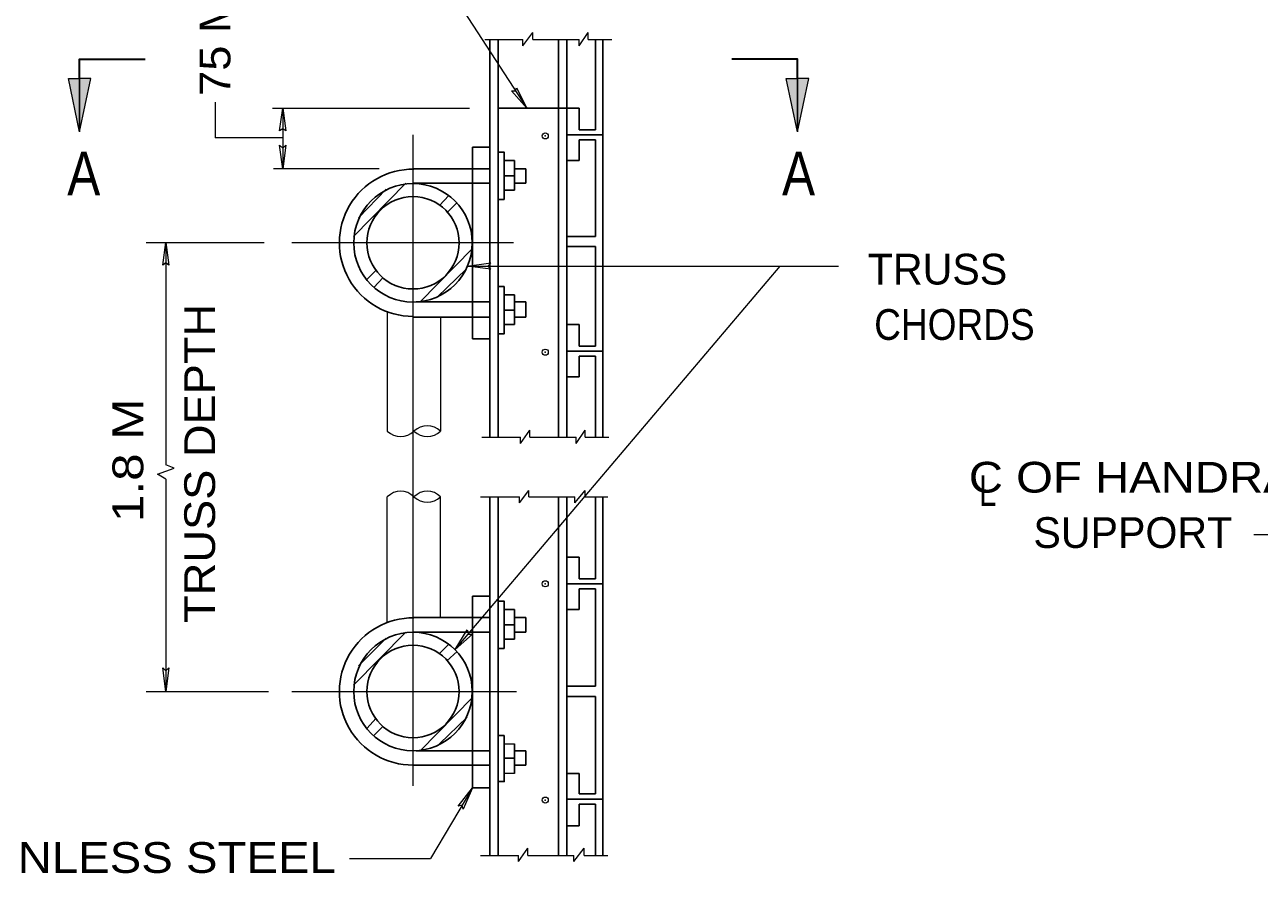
# Model space of a CAD drawing. Extents: x 312601.858 to 312602.699, y 144420.109 to 144420.704.
# Drawn here: x 312601.9234 to 312602.0438, y 144420.5352 to 144420.6179 of the extents above; entities that cross this region are included whole.
import ezdxf
from ezdxf.enums import TextEntityAlignment as Align

# ---------------------------------------------------------------- set-up
doc = ezdxf.new("R2010")
doc.units = 0
doc.header["$LTSCALE"] = 0.0012
doc.header["$PDMODE"] = 32
doc.header["$PDSIZE"] = 0.0006
doc.linetypes.add('DOT_DASHED', pattern=[7.7, 5, -1.2, 0.3, -1.2])
doc.linetypes.add('MEDIUM_DASHED', pattern=[4.5, 3, -1.5])
for name, color, linetype, lineweight in [('1', 7, 'Continuous', 13), ('2', 7, 'Continuous', 13), ('5', 7, 'Continuous', 25)]:
    doc.layers.add(name, color=color, linetype=linetype, lineweight=lineweight)

msp = doc.modelspace()

# ---------------------------------------------------------------- hatches: boundary and pattern name
at = {"layer": '1'}
for points in [[(312601.9277, 144420.6127), (312601.9288, 144420.6127), (312601.9288, 144420.6075)], [(312601.9299, 144420.6127), (312601.9288, 144420.6127), (312601.9288, 144420.6075)], [(312601.9977, 144420.6127), (312601.9988, 144420.6127), (312601.9988, 144420.6075)], [(312601.9999, 144420.6127), (312601.9988, 144420.6127), (312601.9988, 144420.6075)]]:
    msp.add_hatch(color=256, dxfattribs=at).paths.add_polyline_path(points)

# ---------------------------------------------------------------- linework, layer by layer
for p, q in [((312601.9586, 144420.6311), (312601.9724, 144420.6098)), ((312601.9683, 144420.6165), (312601.972, 144420.6165)), ((312601.972, 144420.6159), (312601.973, 144420.6172)), ((312601.972, 144420.6159), (312601.972, 144420.6165)), ((312601.973, 144420.6165), (312601.973, 144420.6172)), ((312601.973, 144420.6165), (312601.9775, 144420.6165)), ((312601.9775, 144420.6159), (312601.9784, 144420.6172)), ((312601.9775, 144420.6159), (312601.9775, 144420.6165)), ((312601.9784, 144420.6165), (312601.9784, 144420.6172)), ((312601.9784, 144420.6165), (312601.9807, 144420.6165)), ((312601.9288, 144420.6077), (312601.9288, 144420.6145)), ((312601.9988, 144420.6077), (312601.9988, 144420.6145)), ((312601.942, 144420.6104), (312601.942, 144420.6069)), ((312601.9476, 144420.6098), (312601.9668, 144420.6098)), ((312601.9486, 144420.6098), (312601.9486, 144420.6039)), ((312601.958, 144420.6039), (312601.9477, 144420.6039)), ((312601.9555, 144420.5973), (312601.9606, 144420.6025)), ((312601.956, 144420.5991), (312601.9587, 144420.6019)), ((312601.9639, 144420.6003), (312601.9648, 144420.6013)), ((312601.9646, 144420.5996), (312601.9656, 144420.6006)), ((312601.9353, 144420.5967), (312601.9468, 144420.5967)), ((312601.9372, 144420.5967), (312601.9372, 144420.575)), ((312601.962, 144420.5909), (312601.9671, 144420.5961)), ((312601.9568, 144420.5931), (312601.9577, 144420.594)), ((312601.9637, 144420.5914), (312601.9665, 144420.5941)), ((312601.9654, 144420.557), (312601.9971, 144420.5944)), ((312601.9666, 144420.5944), (312602.0028, 144420.5944)), ((312601.9575, 144420.5923), (312601.9584, 144420.5933)), ((312601.9588, 144420.59), (312601.9588, 144420.5783)), ((312601.964, 144420.5894), (312601.964, 144420.5783)), ((312601.9718, 144420.5771), (312601.9727, 144420.5784)), ((312601.9727, 144420.5777), (312601.9727, 144420.5784)), ((312601.9772, 144420.5771), (312601.9781, 144420.5784)), ((312601.9781, 144420.5777), (312601.9781, 144420.5784)), ((312601.968, 144420.5777), (312601.9718, 144420.5777)), ((312601.9718, 144420.5771), (312601.9718, 144420.5777)), ((312601.9727, 144420.5777), (312601.9772, 144420.5777)), ((312601.9772, 144420.5771), (312601.9772, 144420.5777)), ((312601.9781, 144420.5777), (312601.9804, 144420.5777)), ((312601.9372, 144420.5736), (312601.9372, 144420.5529)), ((312601.9588, 144420.5596), (312601.9588, 144420.5719)), ((312601.964, 144420.5601), (312601.964, 144420.5719)), ((312601.9679, 144420.5719), (312601.9717, 144420.5719)), ((312601.9717, 144420.5713), (312601.9726, 144420.5725)), ((312601.9717, 144420.5713), (312601.9717, 144420.5719)), ((312601.9726, 144420.5719), (312601.9726, 144420.5725)), ((312601.9726, 144420.5719), (312601.9771, 144420.5719)), ((312601.9771, 144420.5713), (312601.9781, 144420.5725)), ((312601.9771, 144420.5713), (312601.9771, 144420.5719)), ((312601.9781, 144420.5719), (312601.9781, 144420.5725)), ((312601.9781, 144420.5719), (312601.9803, 144420.5719)), ((312602.0433, 144420.5682), (312602.0595, 144420.5682)), ((312601.9555, 144420.5535), (312601.9606, 144420.5587)), ((312601.956, 144420.5554), (312601.9587, 144420.5581)), ((312601.9639, 144420.5566), (312601.9648, 144420.5575)), ((312601.9646, 144420.5559), (312601.9656, 144420.5568)), ((312601.9353, 144420.5529), (312601.9472, 144420.5529)), ((312601.962, 144420.5471), (312601.9671, 144420.5523)), ((312601.9568, 144420.5493), (312601.9577, 144420.5503)), ((312601.9639, 144420.5478), (312601.9666, 144420.5504)), ((312601.9575, 144420.5486), (312601.9584, 144420.5495)), ((312601.9702, 144420.5478), (312601.9712, 144420.5478)), ((312601.9712, 144420.5449), (312601.9702, 144420.5449)), ((312601.9671, 144420.5435), (312601.963, 144420.5366)), ((312601.9716, 144420.5363), (312601.9725, 144420.5376)), ((312601.9725, 144420.5369), (312601.9725, 144420.5376)), ((312601.977, 144420.5363), (312601.978, 144420.5376)), ((312601.978, 144420.5369), (312601.978, 144420.5376)), ((312601.9551, 144420.5366), (312601.963, 144420.5366)), ((312601.9679, 144420.5369), (312601.9716, 144420.5369)), ((312601.9716, 144420.5363), (312601.9716, 144420.5369)), ((312601.9725, 144420.5369), (312601.977, 144420.5369)), ((312601.977, 144420.5363), (312601.977, 144420.5369)), ((312601.978, 144420.5369), (312601.9803, 144420.5369))]:
    msp.add_line(p, q, dxfattribs=at)
at = {"layer": '1', "lineweight": 25}
for p, q in [((312601.9688, 144420.6165), (312601.9688, 144420.5777)), ((312601.9696, 144420.6165), (312601.9696, 144420.5777)), ((312601.9755, 144420.6165), (312601.9755, 144420.5777)), ((312601.9763, 144420.6165), (312601.9763, 144420.5777)), ((312601.9791, 144420.6165), (312601.9791, 144420.6077)), ((312601.9798, 144420.6165), (312601.9798, 144420.5777)), ((312601.9696, 144420.6098), (312601.9775, 144420.6098)), ((312601.9775, 144420.6098), (312601.9775, 144420.6077)), ((312601.9775, 144420.6077), (312601.9791, 144420.6077)), ((312601.9671, 144420.606), (312601.9688, 144420.606)), ((312601.9671, 144420.606), (312601.9671, 144420.5873)), ((312601.9775, 144420.6067), (312601.9791, 144420.6067)), ((312601.9775, 144420.6067), (312601.9775, 144420.6047)), ((312601.9791, 144420.6067), (312601.9791, 144420.5973)), ((312601.9702, 144420.6047), (312601.9712, 144420.6047)), ((312601.9712, 144420.6047), (312601.9712, 144420.6018)), ((312601.9775, 144420.6047), (312601.9763, 144420.6047)), ((312601.967, 144420.6039), (312601.9613, 144420.6039)), ((312601.9712, 144420.6032), (312601.9702, 144420.6032)), ((312601.9712, 144420.6039), (312601.9723, 144420.6039)), ((312601.9723, 144420.6039), (312601.9723, 144420.6025)), ((312601.9613, 144420.6025), (312601.9671, 144420.6025)), ((312601.9712, 144420.6025), (312601.9723, 144420.6025)), ((312601.9696, 144420.6009), (312601.9702, 144420.6009)), ((312601.9702, 144420.6018), (312601.9712, 144420.6018)), ((312601.9763, 144420.5973), (312601.9791, 144420.5973)), ((312601.9763, 144420.5963), (312601.9791, 144420.5963)), ((312601.9791, 144420.5963), (312601.9791, 144420.5866)), ((312601.9696, 144420.5924), (312601.9702, 144420.5924)), ((312601.9702, 144420.5916), (312601.9712, 144420.5916)), ((312601.9712, 144420.5887), (312601.9712, 144420.5916)), ((312601.9616, 144420.5909), (312601.9671, 144420.5909)), ((312601.9712, 144420.5901), (312601.9702, 144420.5901)), ((312601.9712, 144420.5909), (312601.9723, 144420.5909)), ((312601.9723, 144420.5894), (312601.9723, 144420.5909)), ((312601.9613, 144420.5894), (312601.9671, 144420.5894)), ((312601.9712, 144420.5887), (312601.9702, 144420.5887)), ((312601.9712, 144420.5894), (312601.9723, 144420.5894)), ((312601.9763, 144420.5887), (312601.9775, 144420.5887)), ((312601.9775, 144420.5887), (312601.9775, 144420.5866)), ((312601.9671, 144420.5873), (312601.9688, 144420.5873)), ((312601.9775, 144420.5866), (312601.9791, 144420.5866)), ((312601.9763, 144420.5861), (312601.9798, 144420.5861)), ((312601.9775, 144420.5856), (312601.9791, 144420.5856)), ((312601.9775, 144420.5856), (312601.9775, 144420.5836)), ((312601.9791, 144420.5856), (312601.9791, 144420.5777)), ((312601.9775, 144420.5836), (312601.9763, 144420.5836)), ((312601.9688, 144420.5719), (312601.9688, 144420.5369)), ((312601.9696, 144420.5719), (312601.9696, 144420.5369)), ((312601.9755, 144420.5719), (312601.9755, 144420.5369)), ((312601.9763, 144420.5719), (312601.9763, 144420.5369)), ((312601.9791, 144420.5719), (312601.9791, 144420.5639)), ((312601.9798, 144420.5719), (312601.9798, 144420.5369)), ((312601.9763, 144420.566), (312601.9775, 144420.566)), ((312601.9775, 144420.566), (312601.9775, 144420.5639)), ((312601.9775, 144420.5639), (312601.9791, 144420.5639)), ((312601.9671, 144420.5622), (312601.9688, 144420.5622)), ((312601.9671, 144420.5622), (312601.9671, 144420.5435)), ((312601.9763, 144420.5634), (312601.9798, 144420.5634)), ((312601.9775, 144420.5629), (312601.9791, 144420.5629)), ((312601.9775, 144420.5629), (312601.9775, 144420.5609)), ((312601.9791, 144420.5629), (312601.9791, 144420.5534)), ((312601.9613, 144420.5601), (312601.9671, 144420.5601)), ((312601.9702, 144420.5609), (312601.9712, 144420.5609)), ((312601.9712, 144420.5609), (312601.9712, 144420.558)), ((312601.9712, 144420.5601), (312601.9723, 144420.5601)), ((312601.9723, 144420.5601), (312601.9723, 144420.5587)), ((312601.9775, 144420.5609), (312601.9763, 144420.5609)), ((312601.9613, 144420.5587), (312601.9671, 144420.5587)), ((312601.9712, 144420.5594), (312601.9702, 144420.5594)), ((312601.9712, 144420.5587), (312601.9723, 144420.5587)), ((312601.9702, 144420.558), (312601.9712, 144420.558)), ((312601.9696, 144420.5571), (312601.9702, 144420.5571)), ((312601.9763, 144420.5534), (312601.9791, 144420.5534)), ((312601.9763, 144420.5524), (312601.9791, 144420.5524)), ((312601.9791, 144420.5524), (312601.9791, 144420.5429)), ((312601.9696, 144420.5486), (312601.9702, 144420.5486)), ((312601.9712, 144420.5449), (312601.9712, 144420.5478)), ((312601.9616, 144420.5471), (312601.9671, 144420.5471)), ((312601.9712, 144420.5471), (312601.9723, 144420.5471)), ((312601.9723, 144420.5457), (312601.9723, 144420.5471)), ((312601.9613, 144420.5457), (312601.9671, 144420.5457)), ((312601.9712, 144420.5464), (312601.9702, 144420.5464)), ((312601.9712, 144420.5457), (312601.9723, 144420.5457)), ((312601.9763, 144420.5449), (312601.9775, 144420.5449)), ((312601.9775, 144420.5449), (312601.9775, 144420.5429)), ((312601.9671, 144420.5435), (312601.9688, 144420.5435)), ((312601.9763, 144420.5424), (312601.9798, 144420.5424)), ((312601.9775, 144420.5429), (312601.9791, 144420.5429)), ((312601.9775, 144420.5419), (312601.9791, 144420.5419)), ((312601.9775, 144420.5419), (312601.9775, 144420.5398)), ((312601.9791, 144420.5419), (312601.9791, 144420.5369)), ((312601.9775, 144420.5398), (312601.9763, 144420.5398))]:
    msp.add_line(p, q, dxfattribs=at)
at = {"layer": '1', "linetype": 'DOT_DASHED'}
for p, q in [((312601.9613, 144420.6072), (312601.9613, 144420.5437)), ((312601.9495, 144420.5967), (312601.9711, 144420.5967)), ((312601.9495, 144420.5529), (312601.9714, 144420.5529))]:
    msp.add_line(p, q, dxfattribs=at)
at = {"layer": '1', "linetype": 'MEDIUM_DASHED', "lineweight": 25}
for p, q in [((312601.9671, 144420.6039), (312601.9688, 144420.6039)), ((312601.9671, 144420.6025), (312601.9688, 144420.6025)), ((312601.9671, 144420.5909), (312601.9688, 144420.5909)), ((312601.9671, 144420.5894), (312601.9688, 144420.5894)), ((312601.9671, 144420.5601), (312601.9688, 144420.5601)), ((312601.9671, 144420.5587), (312601.9688, 144420.5587)), ((312601.9671, 144420.5471), (312601.9688, 144420.5471)), ((312601.9671, 144420.5457), (312601.9688, 144420.5457))]:
    msp.add_line(p, q, dxfattribs=at)
at = {"layer": '1', "lineweight": 35}
for points in [[(312601.9288, 144420.6127), (312601.9288, 144420.6146), (312601.9352, 144420.6146)], [(312601.9988, 144420.6127), (312601.9988, 144420.6146), (312601.9924, 144420.6146)]]:
    msp.add_lwpolyline(points, dxfattribs=at)
at = {"layer": '1'}
for points in [[(312601.9277, 144420.6127), (312601.9288, 144420.6127), (312601.9288, 144420.6075)], [(312601.9299, 144420.6127), (312601.9288, 144420.6127), (312601.9288, 144420.6075)], [(312601.9714, 144420.6118), (312601.9724, 144420.6098), (312601.9709, 144420.6115), (312601.9713, 144420.6115)], [(312601.9977, 144420.6127), (312601.9988, 144420.6127), (312601.9988, 144420.6075)], [(312601.9999, 144420.6127), (312601.9988, 144420.6127), (312601.9988, 144420.6075)], [(312601.9483, 144420.6076), (312601.9486, 144420.6098), (312601.9489, 144420.6076), (312601.9486, 144420.6078)], [(312601.9489, 144420.6062), (312601.9486, 144420.6039), (312601.9483, 144420.6062), (312601.9486, 144420.6059)], [(312601.9369, 144420.5945), (312601.9372, 144420.5967), (312601.9375, 144420.5945), (312601.9372, 144420.5947)], [(312601.9689, 144420.5941), (312601.9666, 144420.5944), (312601.9689, 144420.5947), (312601.9686, 144420.5944)], [(312601.9671, 144420.5585), (312601.9654, 144420.557), (312601.9666, 144420.5589), (312601.9667, 144420.5585)], [(312601.9375, 144420.5552), (312601.9372, 144420.5529), (312601.9369, 144420.5552), (312601.9372, 144420.5549)], [(312601.9657, 144420.5417), (312601.9671, 144420.5435), (312601.9662, 144420.5414), (312601.9661, 144420.5418)]]:
    msp.add_lwpolyline(points, close=True, dxfattribs=at)
at = {"layer": '1', "lineweight": 25}
for points in [[(312601.9696, 144420.6055), (312601.9702, 144420.6055), (312601.9702, 144420.6009)], [(312601.9696, 144420.5878), (312601.9702, 144420.5878), (312601.9702, 144420.5924)], [(312601.9696, 144420.5617), (312601.9702, 144420.5617), (312601.9702, 144420.5571)], [(312601.9696, 144420.5441), (312601.9702, 144420.5441), (312601.9702, 144420.5486)]]:
    msp.add_lwpolyline(points, dxfattribs=at)
for centre, radius in [((312601.961305, 144420.59667), 0.00578), ((312601.961305, 144420.59667), 0.004505), ((312601.961305, 144420.552895), 0.00578), ((312601.961305, 144420.552895), 0.004505)]:
    msp.add_circle(centre, radius, dxfattribs=at)
for centre in [(312601.961305, 144420.59667), (312601.961305, 144420.552895)]:
    msp.add_arc(centre, 0.007183, 89.32408, 269.97928, dxfattribs=at)
at = {"layer": '1'}
for p in [(312601.9742, 144420.6071), (312601.9742, 144420.586), (312601.9742, 144420.5634), (312601.9742, 144420.5423)]:
    msp.add_point(p, dxfattribs=at)
at = {"layer": '2'}
msp.add_line((312601.9486, 144420.6069), (312601.942, 144420.6069), dxfattribs=at)
at = {"layer": '2', "lineweight": 25}
msp.add_line((312601.9763, 144420.6072), (312601.9798, 144420.6072), dxfattribs=at)
at = {"layer": '2'}
for centre, major_axis, start_param, end_param in [((312601.96005, 144420.57961), (0.001351, -0.001289), 4.712389, 6.2673531), ((312601.96265, 144420.57699), (-0.001351, -0.001289), 3.1574249, 4.712389), ((312601.96265, 144420.57961), (0.001351, -0.001289), 4.712389, 6.2673531), ((312601.96005, 144420.57059), (-0.001351, -0.001289), 3.1574249, 4.712389), ((312601.96265, 144420.57059), (-0.001351, -0.001289), 3.1574249, 4.712389), ((312601.96265, 144420.57321), (0.001351, -0.001289), 4.712389, 6.2673531)]:
    msp.add_ellipse(centre, major_axis=major_axis, ratio=0.969426, start_param=start_param, end_param=end_param, dxfattribs=at)
at = {"layer": '5', "lineweight": 13}
msp.add_lwpolyline([(312601.9372, 144420.5736), (312601.9364, 144420.5741), (312601.938, 144420.5747), (312601.9372, 144420.575)], dxfattribs=at)

# ---------------------------------------------------------------- texts
at = {"layer": '2'}
for s, height, width, p in [('75 MM', 0.003, 1.1, (312601.9435, 144420.61775)), ('TRUSS DEPTH', 0.002999, 1.1, (312601.942, 144420.57515)), ('1.8 M', 0.003, 1.2, (312601.935, 144420.57545))]:
    msp.add_text(s, height=height, rotation=90, dxfattribs=dict(at, width=width)).set_placement(p, align=Align.CENTER)
for s, height, width, p in [('A', 0.00425, 0.85, (312601.9292, 144420.6013)), ('A', 0.00425, 0.85, (312601.9989, 144420.6013)), ('CHORDS', 0.003, 0.9, (312602.0141, 144420.5872))]:
    msp.add_text(s, height=height, dxfattribs=dict(at, width=width)).set_placement(p, align=Align.CENTER)
msp.add_text('TRUSS', height=0.003, dxfattribs=at).set_placement((312602.01245, 144420.5926), align=Align.CENTER)
at = {"layer": '2', "width": 1.15}
for s, p in [('C OF HANDRAIL ', (312602.0155, 144420.5723)), ('STAINLESS STEEL', (312601.9125, 144420.5352))]:
    msp.add_text(s, height=0.003, dxfattribs=at).set_placement(p)
at = {"layer": '2'}
msp.add_text('SUPPORT', height=0.003, dxfattribs=at).set_placement((312602.0218, 144420.5669))
at = {"layer": '5', "width": 0.75}
msp.add_text('L', height=0.003, dxfattribs=at).set_placement((312602.0165, 144420.571))

doc.saveas('drawing.dxf')
